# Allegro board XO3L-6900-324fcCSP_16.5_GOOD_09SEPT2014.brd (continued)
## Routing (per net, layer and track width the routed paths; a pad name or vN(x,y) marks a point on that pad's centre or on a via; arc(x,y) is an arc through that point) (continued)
PT32B: length 7.5
  BOTTOM w0.089: 9.21,16.57 9.21,16.35 9.36,16.2 10.57,16.2 10.7,16.07 10.7,15.7 v1(10.95,15.45)
  BOTTOM w0.102: 9.21,16.57 9.21,16.66 9.04,16.82 9.04,21.45
PT33A: length 7.7
  BOTTOM w0.089: v1(11.95,13.95) 12.2,14.2 12.2,15.76 12.2,17.14
  BOTTOM w0.102: 12.2,17.14 12.2,17.27 12.05,17.42 12.05,21.45
PT33B: length 6.6
  BOTTOM w0.089: 11.7,17.14 11.7,15.79 11.61,15.7 11.2,15.7 v1(10.95,15.95)
  BOTTOM w0.102: 11.7,17.14 11.7,17.26 11.86,17.42 11.86,21.45
PT33C: length 5.2
  L4_SIGNAL2 w0.089: 10.2,17.07 10.2,16.7 v1(10.45,16.45)
  L4_SIGNAL2 w0.102: 10.36,21.45 10.36,17.45 10.2,17.29 10.2,17.07
PT33D: length 5.2
  L4_SIGNAL2 w0.089: v1(10.95,16.45) 10.7,16.7 10.7,17.07
  L4_SIGNAL2 w0.102: 10.55,21.45 10.55,17.45 10.7,17.3 10.7,17.07
PT34A: length 4.5
  L3_SIGNAL1 w0.102: v1(9.95,16.95) 9.95,17.26 10,17.31 10,20.73 10.01,20.74 10.01,21.45
PT34B: length 7
  L3_SIGNAL1 w0.089: 10.21,17.29 10.21,15.35 10.36,15.2 10.7,15.2 v1(10.95,14.95)
  L3_SIGNAL1 w0.102: 10.21,17.29 10.21,20.73 10.2,20.74 10.2,21.45
PT34C: length 7.6
  L6_SIG3 w0.089: 10.84,17.55 10.84,17.43 10.7,17.29 10.7,14.85 10.85,14.7 11.2,14.7 v1(11.45,14.45)
  L6_SIG3 w0.102: 10.84,21.45 10.84,17.55
PT34D: length 4.6
  L6_SIG3 w0.102: v1(10.45,16.95) 10.45,17.32 10.64,17.51 10.64,21.45
PT35A: length 6.2
  L6_SIG3 w0.089: v1(9.95,15.45) 9.7,15.7 9.7,16.51
  L6_SIG3 w0.102: 9.7,16.51 9.7,16.73 9.61,16.82 9.61,17.23 9.82,17.44 9.82,21.45
PT35B: length 5.7
  L6_SIG3 w0.089: 10.2,17.15 10.2,16.2 v1(10.45,15.95)
  L6_SIG3 w0.102: 10.01,21.45 10.01,17.48 10.2,17.29 10.2,17.15
PT35C: length 7
  L4_SIGNAL2 w0.089: v1(10.45,15.45) 10.2,15.7 8.64,15.7 8.56,15.78
  L4_SIGNAL2 w0.102: 8.56,15.78 8.33,16.01 3.64,16.01
PT35D: length 5.4
  L4_SIGNAL2 w0.102: v1(8.95,16.45) 8.71,16.21 3.64,16.21
PT36A: length 4.6
  TOP w0.102: BGA.A3 9.45,17.3 9.3,17.45 9.3,21.45
PT36B: length 4.6
  TOP w0.102: 9.1,21.45 9.1,17.45 8.95,17.3 BGA.A2
PT36C: length 6
  L3_SIGNAL1 w0.089: v1(9.95,15.95) 9.7,16.2 9.7,16.55 9.55,16.7 9.4,16.7 9.25,16.84
  L3_SIGNAL1 w0.102: 9.08,21.45 9.08,17.02 9.25,16.84
PT36D: length 5.5
  L3_SIGNAL1 w0.089: 9.41,16.97 9.48,16.9 9.64,16.9 9.9,16.64 9.9,16.4 v1(9.95,16.45)
  L3_SIGNAL1 w0.102: 9.27,21.45 9.27,17.1 9.41,16.97

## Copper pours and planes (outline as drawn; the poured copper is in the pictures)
GND on L2_GND: 3.58,21.45 11.45,21.45 11.45,13.07 13.95,13.07 13.95,21.45 21.82,21.45 21.82,4.02 3.58,4.02
VCC on L5_PWR: 11.64,11.58 11.26,11.58 11.26,21.45 14.14,21.45 14.14,11.58 13.76,11.58 13.76,12.26 11.64,12.26
VCCIO0 on L2_GND: 11.58,13.2 11.58,21.45 13.82,21.45 13.82,13.2
VCCIO1 on L5_PWR: 3.58,21.45 3.58,4.02 11.14,4.02 11.14,21.45
VCCIO2 on L5_PWR: 11.26,11.45 11.26,4.02 14.14,4.02 14.14,11.45 13.64,11.45 13.64,12.14 11.76,12.14 11.76,11.45
VCCIO3 on L5_PWR: 14.26,12.14 14.26,4.02 21.82,4.02 21.82,12.14
VCCIO4 on L5_PWR: 14.26,13.14 14.26,12.26 21.82,12.26 21.82,13.14
VCCIO5 on L5_PWR: 14.26,13.26 14.26,21.45 21.82,21.45 21.82,13.26

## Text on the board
User.Comments: ASP | XXXXXXXX | 09/03/14 | MM/DD/YY | DWG NO: | XO3L-69E-324FCCSP | REVISION | 1.0 | SHEET | 1 | OF | LATTICE SEMICONDUCTOR CORPORATION | XO3L-69E-324FCCSP PCB BREAKOUT
Ref Des/Silkscreen Top: A | B | C | D | E | F | G | H | J | K | L | M | N | P | R | T | U | V | 1 | 2 | 3 | 4 | 5 | 6 | 7 | 8 | 9 | 10 | 11 | 12 | 13 | 14 | 15 | 16 | 17 | 18 | PCB BREAKOUT | XO3L-69E-324fcCSP | SEMICONDUCTOR | LATTICE
PAGE_OUTLINE: SPECIAL INSTRUCTIONS: | LIKE VIA FILL | SPECIFY ANY SPECIAL INSTRUCTIONS | POWER   PLANE  (L7) | SECONDARY SIDE (L8) | SECONDARY SILKSCREEN | GND     PLANE  (L5) | SECONDARY SOLDERMASK | GND     PLANE  (L2) | PRIMARY SIDE   (L1) | PRIMARY SOLDERMASK | PRIMARY SILKSCREEN | SIGNAL 4       (L4) | SIGNAL 3       (L3) | SIGNAL 3       (L6) | DESIGNED BY: | APPROVED BY: | SIGNATURES         DATE | REV | 1 | INITIAL RELEASE | SPACE/NECK DOWN SPACE | ESCAPE VIA DRILL | TRACE WIDTH/NECK DWN | ESCAPE VIA PAD | LAND OPENING | PACKAGE SIZE | LAND PAD | PITCH | DESCRIPTION | 0.3048 | 0.50 | 0.2235 | 10 X 10 | 0.1016 | 0.127 | 0.08636 | MM | 09/14/2014 | DATE | 4.0/3.5 | 12 | 19.68 | 8.8 | 5.00 | 3.4 | MILS | APPEOVED | X. XXXXX | 8 LAYER STACKUP | PCB BREAKOUT DETAILS | REVISION
